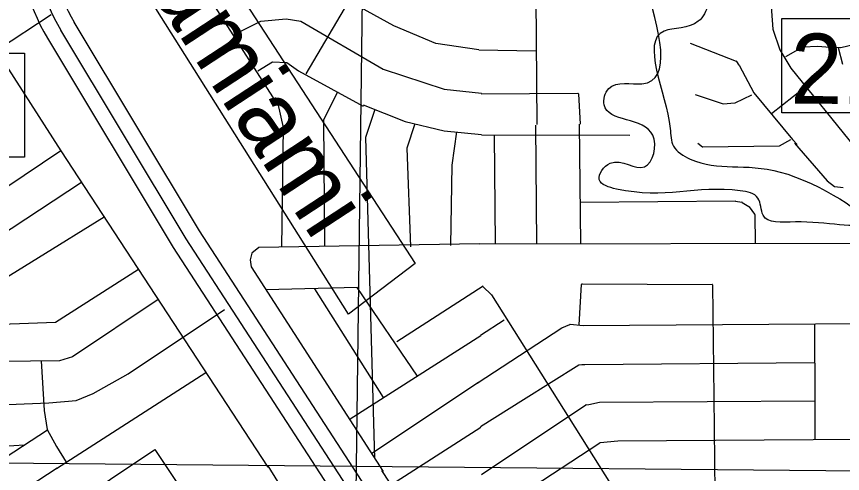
# Model space of a CAD drawing. Extents: x 408847 to 817539, y 923858 to 1151780.
# Drawn here: x 518063 to 523368, y 992795 to 995728 of the extents above; entities that cross this region are included whole.
import ezdxf

# ---------------------------------------------------------------- set-up
doc = ezdxf.new("R2010")
doc.units = 0
for name, color, linetype in [('Lakes and Ponds', 7, 'Continuous'), ('Level 39', 7, 'Continuous'), ('Level 43', 7, 'Continuous'), ('Level 6', 7, 'Continuous'), ('Local Roads Paved', 7, 'Continuous'), ('Masks for Text', 7, 'Continuous'), ('Narrow River Creek and Branch and Slough', 7, 'Continuous'), ('Section Lines', 7, 'Continuous'), ('US Highways Related Text', 7, 'Continuous'), ('US Routes Highway Center Lines', 7, 'Continuous')]:
    doc.layers.add(name, color=color, linetype=linetype)

msp = doc.modelspace()

# ---------------------------------------------------------------- linework, layer by layer
at = {"layer": 'Lakes and Ponds'}
msp.add_spline([(522098, 995959.1), (522080, 995296.4), (521867.2, 995265.9), (521836.8, 995160.3), (522149.6, 994966.5), (522096.7, 994763.2), (521876.2, 994786.6), (521806, 994681.3), (521916.9, 994620.6), (522711.8, 994609.2), (522824.8, 994562.6), (522857.9, 994452.5), (523066.3, 994409.2), (523511.4, 994398.2), (522968.9, 994729.3), (522389.1, 994813.1), (522282.3, 994895.7), (522261.1, 995009.6), (522223.2, 995634.8), (522442.2, 995697.2), (522500.5, 995800.6), (522098, 995959.1)], degree=3, dxfattribs=at)
at = {"layer": 'Level 39'}
msp.add_lwpolyline([(522979, 995715), (523916.9, 995715), (523916.9, 995110.6), (522979, 995110.6)], close=True, dxfattribs=at)
at = {"layer": 'Level 6'}
for p, q in [((519237.8, 994351.9), (518433.6, 995691.5)), ((518262.1, 995588.6), (519068.2, 994245.9)), ((523321, 988074.6), (519237.8, 994351.9)), ((519068.2, 994245.9), (523153.3, 987965.6))]:
    msp.add_line(p, q, dxfattribs=at)
for centre, radius, start, end in [((519376.6, 996257.7), 1300, 177.0174, 210.9781), ((519376.7, 996257.7), 1100, 177.0178, 210.9784)]:
    msp.add_arc(centre, radius, start, end, dxfattribs=at)
at = {"layer": 'Local Roads Paved'}
for p, q in [((518676.9, 996831.6), (519741.1, 995158.4)), ((521393.3, 996609), (521404.6, 995035.1)), ((522891.8, 996058.2), (522920.3, 995647.5)), ((518284.5, 995738.1), (516744.6, 994732.3)), ((522920.5, 995646.5), (522965.3, 995514.9)), ((522390.7, 995556.8), (522685.3, 995441.7)), ((523004.9, 995472.2), (523113.9, 995533.7)), ((523115.7, 995534.3), (523207.5, 995537)), ((523207.9, 995537), (523289.4, 995531.4)), ((523289.5, 995531.4), (523356.5, 995528.6)), ((523340.1, 995528.6), (523368.1, 995422.3)), ((523357.6, 995528.7), (523446.7, 995551)), ((521032.4, 995514.4), (521398.9, 995508.7)), ((522965.6, 995514.1), (523035.7, 995396.3)), ((522687.2, 995440.2), (522703.3, 995416)), ((522703.5, 995415.7), (522799, 995238.6)), ((523036, 995395.9), (523444.4, 994891.5)), ((522911.9, 995105.8), (523123.2, 995272.1)), ((521046.8, 995232.4), (521668.4, 995235.2)), ((521672.4, 995231.4), (521683.5, 995037.9)), ((522421.7, 995227), (522601.2, 995168)), ((522678.7, 995173.7), (522785.1, 995224.2)), ((522799.4, 995237.9), (523047.1, 994939.5)), ((522602.8, 995167.8), (522677.3, 995173.4)), ((521404.3, 994267.5), (521398.7, 995031.4)), ((521677.6, 995037), (521686.1, 994269.7)), ((521049.3, 994969.4), (522001.6, 994966.5)), ((521131, 994969.4), (521136.6, 994268.9)), ((522963.5, 994897.7), (523035.9, 994939.5)), ((523047.2, 994939.4), (523078.1, 994905.6)), ((522438.6, 994914.1), (522468.5, 994892.3)), ((522470.9, 994891.5), (522961.6, 994897.2)), ((523060.9, 994915.8), (523269.1, 994673.7)), ((518348.3, 994864.8), (519677.3, 992836)), ((523269.8, 994673.1), (523316.4, 994637.4)), ((518480.7, 994662.6), (517529.3, 994038.1)), ((523318.4, 994636.6), (523372.9, 994631.2)), ((521683.2, 994535.3), (522680.2, 994543.7)), ((522681, 994543.6), (522722.1, 994535.4)), ((522723.5, 994534.9), (522767.3, 994507.5)), ((522768.4, 994506.5), (522803.7, 994460.2)), ((522804.6, 994457.8), (522807.4, 994270.3)), ((521035.8, 994268.7), (524002, 994273.1)), ((520506.1, 993640.7), (521060.3, 993998.9)), ((521057.7, 993994.6), (521113.7, 993941.4)), ((521677.6, 993749.4), (521691.5, 994007.7)), ((521695.5, 994011.5), (522530.1, 994008.7)), ((522534.1, 994004.8), (522542.5, 993287.1)), ((519976.5, 993979.2), (520417.8, 993282.5)), ((521114.4, 993940.6), (521539.5, 993264.5)), ((521043.7, 993681.7), (521195.8, 993780.4)), ((521021.1, 993374.5), (521564.6, 993729.5)), ((521565.2, 993729.8), (521617.5, 993751.8)), ((521619.4, 993752.1), (521702.7, 993743.8)), ((521703.1, 993743.8), (523906.2, 993760.7)), ((523187.7, 993749.4), (523190.5, 993261.7)), ((520207, 993145.1), (521045.6, 993679.9)), ((523189.1, 993504.2), (521714.2, 993492.9)), ((521674, 993489.6), (521319.8, 993267.4)), ((521694.2, 993492.8), (521675.6, 993490.2)), ((521714.2, 993492.9), (521694.8, 993492.9)), ((518318.9, 992826.2), (519279.5, 993443.3)), ((520344.3, 992924.3), (521030.9, 993380.6)), ((521319.8, 993267.4), (521043.7, 993093.8)), ((521539.5, 993264.5), (521877.6, 992728.2)), ((521720.7, 993234.8), (521739.4, 993237.5)), ((521739.7, 993237.5), (521806.8, 993251.5)), ((521807.6, 993251.6), (523190.5, 993261.7)), ((522542.5, 993287.1), (522562.2, 991145)), ((523190.5, 993261.7), (523189.8, 993012.1)), ((521050.5, 992788.4), (521719.1, 993234.2)), ((520471.8, 992724.6), (521045.6, 993092.6)), ((518262, 993072.8), (517614.1, 992650.9)), ((521026.8, 992479.2), (521809.2, 992991.7)), ((521811, 992992.4), (521925.3, 993003.5)), ((521925.7, 993003.5), (524010.4, 993017.6)), ((518323.8, 992829.6), (517704.2, 992424.7)), ((519677.3, 992843.9), (520349.2, 991749.9)), ((520408, 992812.8), (521026, 991880.6))]:
    msp.add_line(p, q, dxfattribs=at)
for points in [[(519922.5, 995359.6), (520780.8, 996816.8), (520844.5, 996846.3), (520893.5, 996856.1)], [(521032.4, 995514.4), (520756.2, 995555.8), (520486.5, 995668.7), (520187.3, 995835.5), (519961.8, 995943.5), (519746, 995977.8), (519495.9, 995933.6), (519304.6, 995840.4)], [(516759.3, 994747), (516705.4, 994884.4), (516705.4, 994997.2), (516710.3, 995031.6), (517475.4, 995502.6), (517794.1, 995723.4), (518348.3, 994864.8), (517995.2, 994629.2), (517725.5, 995061)], [(519456.6, 995609.8), (519633.2, 995698.1), (519795, 995712.8), (519888.2, 995698.1), (520417.8, 995389), (520810.2, 995261.4), (521050.5, 995236.9)], [(519613.6, 995379.2), (519706.7, 995438.1), (519799.9, 995433.2), (519873.5, 995379.2), (520290.3, 995153.5)], [(520123.6, 995245.1), (520035.3, 995063.6), (520040.3, 994251.5)], [(519741.1, 995166.6), (519775.4, 995014.5), (519765.4, 994246.7)], [(520290.3, 995161.7), (520560.1, 995053.8), (520810.2, 994994.9), (521050.5, 994970.4)], [(520365.3, 995131.7), (520305, 994950.7), (520363, 992891.5)], [(520620.6, 995039.5), (520569.9, 994882.1), (520594.4, 994249.1)], [(520888.9, 994986.9), (520859.2, 994774.1), (520849.4, 994258.9)], [(517789.6, 993511.8), (517779.4, 993920.4), (518625.6, 994441.4)], [(521035.8, 994268.7), (519618.5, 994244.2), (519574.3, 994209.8), (519564.5, 994165.7), (519569.4, 994121.5), (520417.8, 992806.6)], [(518846.3, 994104.6), (518314, 993763.3), (517789.2, 993743.7)], [(520638.5, 993419.9), (520251.1, 993989.1), (519664.7, 993973.9)], [(518972.7, 993911.6), (518421.9, 993542.6), (518338.5, 993518), (517029.1, 993503.3)], [(516813.3, 992801.7), (516823.1, 992958.7), (516832.9, 993002.8), (516852.5, 993066.6), (516886.9, 993130.4), (516950.6, 993169.7), (517058.5, 993194.2), (517161.5, 993204), (518269.8, 993248.2), (518446.4, 993262.9), (518554.3, 993307), (518779.9, 993434.6), (519397.8, 993846.8)], [(518220.8, 993518), (518240.4, 993199.1), (518260, 993076.4), (518318.9, 992968.5), (518381.1, 992866.2)], [(518112.6, 992975.5), (517578.3, 992942.4), (517509.7, 992913), (518049.1, 991558.8), (518284.5, 991092.7), (518338.5, 991038.7), (518966.2, 990552.9), (520268.1, 991375.1)], [(517803.9, 992181.9), (518951.5, 992947.4), (519378.2, 992309.5)]]:
    msp.add_lwpolyline(points, dxfattribs=at)
for centre, start, end in [((522924.3, 995647.8), 183.9705, 198.7912), ((523115.9, 995530.3), 91.7366, 119.4396), ((523207.6, 995533), 86.0529, 91.7366), ((523289.6, 995535.4), 266.0529, 267.6129), ((523356.6, 995532.6), 267.6129, 284.0429), ((522969.1, 995516.2), 198.7912, 210.7502), ((522683.9, 995437.9), 33.6769, 68.6609), ((522700, 995413.8), 28.3431, 33.6769), ((523039.1, 995398.4), 210.7502, 218.9955), ((521668.4, 995231.2), 3.2689, 90.2582), ((522802.5, 995240.5), 208.3431, 219.6851), ((522602.5, 995171.8), 251.8256, 274.2385), ((522677, 995177.3), 274.2385, 295.3572), ((523050.1, 994942.1), 219.6851, 222.4963), ((522470.8, 994895.5), 233.9591, 270.6551), ((522961.5, 994901.2), 270.6551, 299.9939), ((523272.2, 994676.3), 220.6968, 232.5809), ((523318.8, 994640.6), 232.5809, 264.2866), ((522680.2, 994539.7), 78.6846, 90.4858), ((522721.3, 994531.5), 57.9818, 78.6846), ((522765.2, 994504.1), 37.3916, 57.9818), ((522800.6, 994457.8), 0.8547, 37.3916), ((521695.5, 994007.5), 89.8083, 176.9241), ((522530.1, 994004.7), 0.6711, 89.8083), ((521111, 993938.5), 32.1639, 46.4546), ((521566.8, 993726.1), 112.8438, 123.1515), ((521619, 993748.1), 84.2866, 112.8438), ((521703.1, 993747.8), 264.2866, 270.4398), ((521676.2, 993486.2), 98.1341, 122.0999), ((521694.8, 993488.9), 90, 98.1341), ((521714.2, 993496.9), 270, 270.4401), ((521738.9, 993241.5), 278.1341, 281.774), ((521807.6, 993247.6), 90.4194, 101.774), ((521721.3, 993230.9), 98.1341, 123.6962), ((521811.4, 992988.4), 95.5749, 123.2248), ((521925.7, 992999.5), 90.3873, 95.5749)]:
    msp.add_arc(centre, 4, start, end, dxfattribs=at)
at = {"layer": 'Masks for Text'}
for points in [[(519079, 996513.1), (520623.7, 994143), (520194.6, 993816.7), (518735.7, 996135.3)], [(517144.8, 995492.3), (518114.5, 995492.3), (518114.5, 994824.2), (517144.8, 994824.2)]]:
    msp.add_lwpolyline(points, close=True, dxfattribs=at)
at = {"layer": 'Narrow River Creek and Branch and Slough'}
for points in [[(523275.5, 996199.2), (524318.1, 995017.6), (524411.5, 994703.5), (524354.6, 994498.2), (523541.5, 994451.9)], [(516202.8, 995500.1), (516424.8, 995410.7), (516656.6, 994638.5), (517022.9, 994088.9), (517177.7, 993728.5), (517269.4, 993126.9), (517600.1, 992274.2), (518031.1, 991265), (518671.4, 990669.7), (519583.4, 989996.6), (520346.1, 989274.7), (520953.5, 988734)]]:
    msp.add_spline(points, degree=3, dxfattribs=at)
at = {"layer": 'Section Lines'}
for p, q in [((520310, 998119.1), (520245.4, 992839.8)), ((520245.4, 992839.8), (514993.6, 992887.9)), ((520245.4, 992839.8), (520180.4, 987527.1)), ((525631.5, 992790.6), (520245.4, 992839.8))]:
    msp.add_line(p, q, dxfattribs=at)
at = {"layer": 'US Routes Highway Center Lines'}
for p, q in [((519152, 994300.5), (518347.8, 995640)), ((523237.2, 988020.1), (519152, 994300.5))]:
    msp.add_line(p, q, dxfattribs=at)
msp.add_arc((519376.7, 996257.7), 1200, 177.0178, 210.9784, dxfattribs=at)

# ---------------------------------------------------------------- texts
at = {"layer": 'Level 43'}
msp.add_text('21', height=450, rotation=359.6504, dxfattribs=at).set_placement((523033.3, 995169.1))
at = {"layer": 'US Highways Related Text'}
msp.add_text('Tamiami', height=450, rotation=303.2117, dxfattribs=at).set_placement((518712.5, 996207.1))

doc.saveas('drawing.dxf')
